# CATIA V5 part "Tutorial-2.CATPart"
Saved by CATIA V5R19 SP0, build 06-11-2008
Part number: Part1
Bounding box of the stored display mesh (mm): x -56 to 56, y -20 to 21, z -12 to 52
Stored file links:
  D:\Shriniwas\v5_r19\Part files\C15\TUT2.CATPart
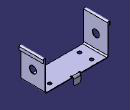
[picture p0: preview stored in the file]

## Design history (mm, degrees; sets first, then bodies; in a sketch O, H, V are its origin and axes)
SheetMetalParameters1: BendRadius 2, ReliefAxialLength 2, ReliefRadialLength 1, MinimumBendRadius 0, Thickness 1, KFactor 0.400515 {= log(min(100,max(20*SheetMetalParameters1.BendRadius,SheetMetalParameters1.Thickness)/SheetMetalParameters1.Thickness))/log(100)/2}
Body1 (main body)
  Sketch1 on xy-plane, origin (0, 0, 0), H (1, 0, 0), V (0, 1, 0)
    line L1 (50, 20) -> (50, -20)
    line L2 (50, -20) -> (-50, -20)
    line L3 (-50, -20) -> (-50, 20)
    line L4 (-50, 20) -> (50, 20)
    length L4 = 100
    length L1 = 40
    vertical: L1 V, L3 V
    horizontal: L2 H, L4 H
    equidistance: L1 L3 O, L2 L4 O
  Wall1: Thickness 1, Profile Sketch1
  Sketch2 on face of Wall1, origin (29.2419, -0.5458, 1), H (1, 0, 0), V (0, 1, 0)
    point P1 (-64.2419, -9.4542)
    reference projected line E1 (-79.2419, -19.4542) -> (-79.2419, 20.5458) from edge [face of Wall1 | face of Wall1]
    reference projected line E2 (20.7581, -19.4542) -> (-79.2419, -19.4542) from edge [face of Wall1 | face of Wall1]
    distance E1 P1 = 15
    distance E2 P1 = 10
  Hole1: placed by Sketch2, at (-35, -10, 1) direction (0, 0, -1), diameter 6, depth 10
  RectPattern1: of Hole1, direction 1 instances 2, spacing 70, along edge [face of Wall1 | face of Wall1] reversed, direction 2 instances 2, spacing 20, along edge [face of Wall1 | face of Wall1]
  Flange1: Length 50, Radius 2, Angle 90, KFacteur 0.400515 {= log(min(100,max(20*Flange1.Radius,SheetMetalParameters1.Thickness)/SheetMetalParameters1.Thickness))/log(100)/2}, Guide edge [face of Wall1 | face of Wall1]
  Flange2: Length 50, Radius 2, Angle 90, KFacteur 0.400515 {= log(min(100,max(20*Flange2.Radius,SheetMetalParameters1.Thickness)/SheetMetalParameters1.Thickness))/log(100)/2}, Guide edge [face of Wall1 | face of Wall1]
  Flange3: Length 5, Radius 1, Angle 90, KFacteur 0.325257 {= log(min(100,max(20*Flange3.Radius,SheetMetalParameters1.Thickness)/SheetMetalParameters1.Thickness))/log(100)/2}, Guide edge [face of Flange2 | face of Flange2]
  Flange4: Length 5, Radius 1, Angle 90, KFacteur 0.325257 {= log(min(100,max(20*Flange4.Radius,SheetMetalParameters1.Thickness)/SheetMetalParameters1.Thickness))/log(100)/2}, Guide edge [face of Flange1 | face of Flange1]
  Sketch3 on face of Flange1, origin (53, 0, 0), H (0, 1, 0), V (0, 0, 1)
    arc A1 centre (0, 25) radius 6 from (-1, 30.9161) to (1, 30.9161) ccw
    point P1 (0, 25)
    line L1 (-1, 30.9161) -> (-1, 29.9161)
    line L2 (-1, 29.9161) -> (1, 29.9161)
    line L3 (1, 29.9161) -> (1, 30.9161)
    radius A1 = 6
    distance H P1 = 25
    length L2 = 2
    distance V L1 = 1
    length L3 = 1
    coincidence: P1 V
    vertical: L1 V, L3 V
    horizontal: L2 H
  CutOut1: StartLimit through (limit type 2), Orientation true, Profile Sketch3, Direction Sketch3, EndLimit through (limit type 3)
  d_NewWallOnEdge1: NewWallOnEdge_HeightLimitOffset 0, NewWallOnEdge_Length 13, NewWallOnEdge_Edge edge [face of Wall1 | face of Wall1], NewWallOnEdge_WidthOffset1 -44, NewWallOnEdge_WidthOffset2 -44, NewWallOnEdge_Angle 90, KFacteur 0.400515 {= log(min(100,max(20*d_NewWallOnEdge1.Radius,SheetMetalParameters1.Thickness)/SheetMetalParameters1.Thickness))/log(100)/2}, NewWallOnEdge_BendRadiusValue 2 {= SheetMetalParameters1.BendRadius}
  Corner1: CornerChamferEdges (edge [face of d_NewWallOnEdge1 | face of d_NewWallOnEdge1]; edge [face of d_NewWallOnEdge1 | face of d_NewWallOnEdge1]), CornerRadius 3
